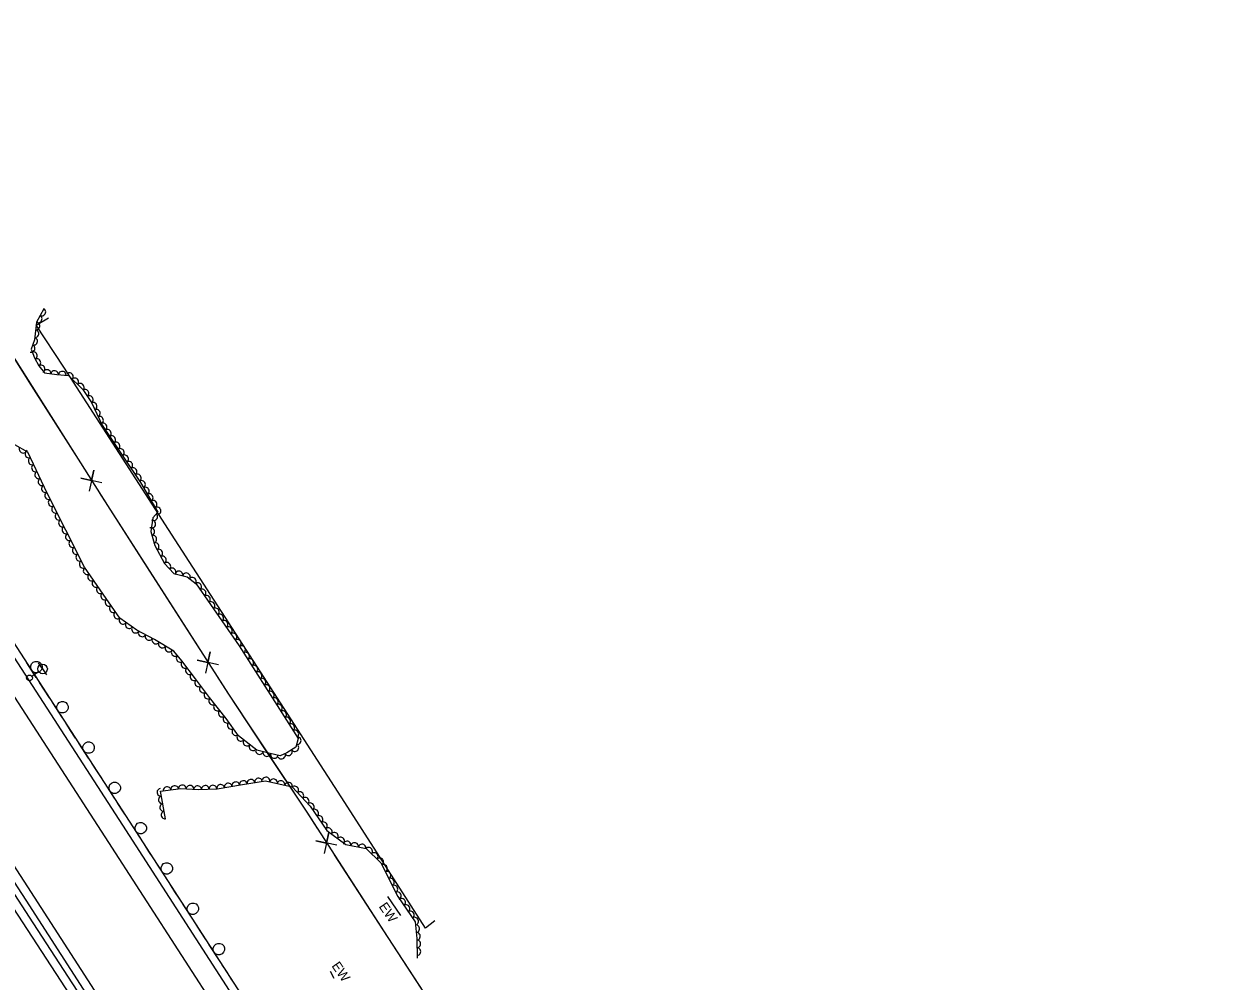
# Model space of a CAD drawing. Extents: x 1746719 to 1766531, y 631721 to 662391.
# Drawn here: x 1760642 to 1761266, y 640505 to 641004 of the extents above; entities that cross this region are included whole.
import ezdxf

# ---------------------------------------------------------------- set-up
doc = ezdxf.new("R2010")
doc.units = 0
for name, color, linetype in [('SURVEY - AERIAL SURVEY - Photo Control - Points - Elevations', 7, 'Continuous'), ('SURVEY - AERIAL SURVEY - Photo Control - Points - Numbers', 7, 'Continuous'), ('SURVEY - AERIAL SURVEY - Photo Control with Text', 7, 'Continuous'), ('SURVEY - CENTERLINE - Existing Roads - Development', 7, 'Continuous'), ('SURVEY - CENTERLINE - Existing Roads Curve Text', 7, 'Continuous'), ('SURVEY - CENTERLINE - Existing Roads Text', 7, 'Continuous'), ('SURVEY - CENTERLINE - Preliminary - Development', 7, 'Continuous')]:
    doc.layers.add(name, color=color, linetype=linetype)

msp = doc.modelspace()

# ---------------------------------------------------------------- linework, layer by layer
at = {"layer": 'SURVEY - AERIAL SURVEY - Photo Control - Points - Elevations'}
for points in [[(1761196.4, 639810.64), (1761146.73, 639886.96), (1761080.18, 639989.67), (1761013.55, 640093.35), (1760935.82, 640212.96), (1760859, 640331.61), (1760773.89, 640462.5), (1760694.04, 640586.22), (1760626.17, 640690.93), (1760539.47, 640824.63), (1760468.8, 640933.89), (1760453.88, 640957.11)], [(1761187.18, 639804.64), (1761137.51, 639880.97), (1761070.94, 639983.7), (1761004.31, 640087.38), (1760926.59, 640206.97), (1760849.77, 640325.63), (1760764.66, 640456.52), (1760684.8, 640580.25), (1760616.94, 640684.94), (1760530.24, 640818.65), (1760459.56, 640927.93), (1760444.62, 640951.16)], [(1761146.95, 639778.46), (1761097.25, 639854.83), (1761030.61, 639957.68), (1760963.99, 640061.33), (1760886.32, 640180.85), (1760809.51, 640299.5), (1760724.37, 640430.42), (1760644.5, 640554.18), (1760576.67, 640658.83), (1760489.95, 640792.56), (1760419.21, 640901.92), (1760404.24, 640925.21)], [(1760393.74, 640918.4), (1760441.13, 640845.23), (1760507.05, 640743.21), (1760565.58, 640652.81), (1760626.82, 640558.41), (1760688.54, 640463.7), (1760741.79, 640381.9), (1760794.12, 640301.16), (1760851.62, 640212.52), (1760925.86, 640097.46), (1760981.18, 640012.09), (1761038.81, 639922.4), (1761095.32, 639835.55), (1761136.33, 639771.93)], [(1760856.45, 640536.45), (1760851.59, 640532.66), (1760811.17, 640595.61), (1760765.67, 640666.2), (1760721.15, 640734.98), (1760663.16, 640824.86), (1760648.84, 640846.78), (1760655.25, 640850.56)]]:
    msp.add_lwpolyline(points, dxfattribs=at)
at = {"layer": 'SURVEY - AERIAL SURVEY - Photo Control - Points - Numbers'}
for points in [[(1761140.67, 639773.85), (1761073.58, 639878.26), (1760990.71, 640006.56), (1760880.55, 640175.62), (1760768.9, 640348.2), (1760647.19, 640535.4), (1760552.29, 640681.96), (1760459.27, 640825.92), (1760396.33, 640923.21)], [(1760398.55, 640924.9), (1760464.19, 640823.64), (1760557.54, 640679.57), (1760643.46, 640547.14), (1760726.42, 640418.31), (1760797.81, 640309.01), (1760889.3, 640167.21), (1760984.42, 640021.34), (1761065.75, 639894.94), (1761143.02, 639775.73)], [(1760925.05, 640236.95), (1760862.35, 640333.79), (1760777.25, 640464.67), (1760697.4, 640588.39), (1760623.82, 640701.9)], [(1760648.9, 640663.22), (1760643.89, 640670.94)], [(1760653.2, 640656.59), (1760650.64, 640660.53)], [(1760655.75, 640652.65), (1760653.2, 640656.59)], [(1760662.5, 640642.24), (1760657.49, 640649.96)], [(1760666.79, 640635.61), (1760664.24, 640639.55)], [(1760669.35, 640631.67), (1760666.79, 640635.61)], [(1760676.09, 640621.26), (1760671.09, 640628.98)], [(1760680.39, 640614.63), (1760677.83, 640618.58)], [(1760682.95, 640610.69), (1760680.39, 640614.63)], [(1760689.69, 640600.28), (1760684.69, 640608)], [(1760693.99, 640593.65), (1760691.43, 640597.6)], [(1760696.54, 640589.71), (1760693.99, 640593.65)], [(1760703.27, 640579.29), (1760698.28, 640587.02)], [(1760707.55, 640572.66), (1760705.01, 640576.6)], [(1760710.1, 640568.71), (1760707.55, 640572.66)], [(1760716.83, 640558.29), (1760711.84, 640566.02)], [(1760721.11, 640551.65), (1760718.56, 640555.6)], [(1760723.66, 640547.7), (1760721.11, 640551.65)], [(1760730.39, 640537.28), (1760725.4, 640545.01)], [(1760734.67, 640530.65), (1760732.12, 640534.59)], [(1760737.22, 640526.7), (1760734.67, 640530.65)], [(1760743.94, 640516.28), (1760738.95, 640524.01)], [(1760748.23, 640509.64), (1760745.68, 640513.59)], [(1760750.77, 640505.69), (1760748.23, 640509.64)]]:
    msp.add_lwpolyline(points, dxfattribs=at)
for centre, start, end in [((1760648.94, 640668.67), 326.21851, 326.20452), ((1760662.54, 640647.69), 326.21851, 326.20452), ((1760676.13, 640626.72), 326.21851, 326.20452), ((1760689.73, 640605.74), 326.21851, 326.20452), ((1760703.32, 640584.75), 326.10698, 326.093), ((1760716.88, 640563.74), 326.10698, 326.093), ((1760730.43, 640542.74), 326.10698, 326.093), ((1760743.99, 640521.73), 326.10698, 326.093)]:
    msp.add_arc(centre, 3, start, end, dxfattribs=at)
at = {"layer": 'SURVEY - AERIAL SURVEY - Photo Control with Text'}
for points in [[(1760652.8, 640855.32), (1760649.07, 640848.29), (1760647.88, 640839.12), (1760646.16, 640834.17), (1760647.95, 640829.76), (1760650.29, 640825.51), (1760653.15, 640821.88), (1760659.59, 640820.97), (1760665.62, 640820.59), (1760673.09, 640813.22), (1760677.66, 640806.53), (1760683.18, 640794.6), (1760694.39, 640778.05), (1760703.24, 640764.75), (1760712.26, 640749.31), (1760709.68, 640746.36), (1760708.59, 640739.29), (1760710.64, 640731.98), (1760715.72, 640722.6), (1760720.5, 640717.38), (1760727.46, 640715.68), (1760732.09, 640711.96), (1760754.62, 640679.75), (1760785.21, 640631.37), (1760784.01, 640626.84), (1760779.46, 640623.97), (1760775.84, 640622.35), (1760770.7, 640623.55), (1760763.77, 640625.42), (1760754.17, 640632.89), (1760747.82, 640641.88), (1760739.17, 640652.85), (1760731.76, 640662.53), (1760724.77, 640671.94), (1760720.57, 640676.86), (1760710.44, 640683.05), (1760701.2, 640687.84), (1760692.42, 640694.05), (1760683.71, 640706.63), (1760674, 640720.66), (1760654.63, 640759.17), (1760644.46, 640780.64), (1760637.69, 640784.42)], [(1760716.22, 640589.64), (1760713.6, 640603.96), (1760724.16, 640605.36), (1760733.14, 640604.88), (1760743.08, 640605.29), (1760756.27, 640607.51), (1760768.2, 640609.47), (1760782.11, 640606.19), (1760791.46, 640596.23), (1760800.24, 640583.55), (1760810.05, 640576.21), (1760820.72, 640574.07), (1760828.34, 640566.74), (1760837.16, 640549.22), (1760846.29, 640536.02), (1760847.09, 640527.3), (1760847.34, 640517.01)]]:
    msp.add_lwpolyline(points, dxfattribs=at)
for centre, major_axis in [((1760651.87, 640853.55), (-0.94, -1.77)), ((1760648.81, 640846.26), (-0.26, -1.98)), ((1760649.99, 640850.02), (-0.94, -1.77)), ((1760648.29, 640842.3), (-0.26, -1.98)), ((1760646.3, 640834.59), (-0.66, -1.89)), ((1760647.62, 640838.37), (-0.66, -1.89)), ((1760647.5, 640830.88), (0.75, -1.85)), ((1760649.3, 640827.31), (0.96, -1.75)), ((1760651.49, 640823.98), (1.24, -1.57)), ((1760654.46, 640821.7), (1.98, -0.28)), ((1760658.42, 640821.14), (1.98, -0.28)), ((1760662.4, 640820.8), (2, -0.13)), ((1760666.17, 640820.04), (1.42, -1.4)), ((1760669.02, 640817.24), (1.42, -1.4)), ((1760671.87, 640814.43), (1.42, -1.4)), ((1760674.38, 640811.34), (1.13, -1.65)), ((1760676.63, 640808.03), (1.13, -1.65)), ((1760678.57, 640804.55), (0.84, -1.82)), ((1760680.25, 640800.92), (0.84, -1.82)), ((1760681.93, 640797.29), (0.84, -1.82)), ((1760683.76, 640793.74), (1.12, -1.66)), ((1760686, 640790.43), (1.12, -1.66)), ((1760688.24, 640787.12), (1.12, -1.66)), ((1760690.49, 640783.81), (1.12, -1.66)), ((1760641.97, 640782.03), (-1.75, 0.97)), ((1760644.95, 640779.6), (-0.86, 1.81)), ((1760692.73, 640780.5), (1.12, -1.66)), ((1760694.97, 640777.18), (1.11, -1.66)), ((1760646.66, 640775.98), (-0.86, 1.81)), ((1760648.38, 640772.37), (-0.86, 1.81)), ((1760697.18, 640773.85), (1.11, -1.66)), ((1760699.4, 640770.52), (1.11, -1.66)), ((1760650.09, 640768.76), (-0.86, 1.81)), ((1760651.8, 640765.14), (-0.86, 1.81)), ((1760701.62, 640767.19), (1.11, -1.66)), ((1760703.78, 640763.83), (1.01, -1.73)), ((1760653.51, 640761.53), (-0.86, 1.81)), ((1760655.25, 640757.92), (-0.9, 1.79)), ((1760705.8, 640760.37), (1.01, -1.73)), ((1760657.05, 640754.35), (-0.9, 1.79)), ((1760707.82, 640756.92), (1.01, -1.73)), ((1760709.83, 640753.47), (1.01, -1.73)), ((1760658.85, 640750.78), (-0.9, 1.79)), ((1760660.65, 640747.21), (-0.9, 1.79)), ((1760710.16, 640746.91), (-1.32, -1.5)), ((1760711.85, 640750.01), (1.01, -1.73)), ((1760662.45, 640743.63), (-0.9, 1.79)), ((1760664.24, 640740.06), (-0.9, 1.79)), ((1760708.62, 640739.18), (0.54, -1.93)), ((1760709.18, 640743.13), (-0.31, -1.98)), ((1760666.04, 640736.49), (-0.9, 1.79)), ((1760667.84, 640732.91), (-0.9, 1.79)), ((1760709.7, 640735.33), (0.54, -1.93)), ((1760669.64, 640729.34), (-0.9, 1.79)), ((1760710.88, 640731.52), (0.95, -1.76)), ((1760712.79, 640728.01), (0.95, -1.76)), ((1760671.44, 640725.77), (-0.9, 1.79)), ((1760673.23, 640722.19), (-0.9, 1.79)), ((1760714.7, 640724.49), (0.95, -1.76)), ((1760716.97, 640721.23), (1.35, -1.48)), ((1760675.3, 640718.78), (-1.14, 1.64)), ((1760677.58, 640715.49), (-1.14, 1.64)), ((1760719.67, 640718.28), (1.35, -1.48)), ((1760723.19, 640716.72), (1.94, -0.47)), ((1760727.08, 640715.77), (1.94, -0.47)), ((1760679.86, 640712.2), (-1.14, 1.64)), ((1760682.13, 640708.91), (-1.14, 1.64)), ((1760730.27, 640713.42), (1.56, -1.25)), ((1760733.05, 640710.59), (1.15, -1.64)), ((1760735.34, 640707.32), (1.15, -1.64)), ((1760684.41, 640705.62), (-1.14, 1.64)), ((1760686.68, 640702.33), (-1.14, 1.64)), ((1760737.63, 640704.04), (1.15, -1.64)), ((1760688.96, 640699.05), (-1.14, 1.64)), ((1760691.24, 640695.76), (-1.14, 1.64)), ((1760739.92, 640700.76), (1.15, -1.64)), ((1760742.22, 640697.48), (1.15, -1.64)), ((1760693.99, 640692.94), (-1.63, 1.15)), ((1760697.25, 640690.63), (-1.63, 1.15)), ((1760744.51, 640694.21), (1.15, -1.64)), ((1760746.8, 640690.93), (1.15, -1.64)), ((1760700.52, 640688.32), (-1.63, 1.15)), ((1760704.01, 640686.38), (-1.78, 0.92)), ((1760707.56, 640684.54), (-1.78, 0.92)), ((1760749.09, 640687.65), (1.15, -1.64)), ((1760751.39, 640684.37), (1.15, -1.64)), ((1760711.09, 640682.65), (-1.71, 1.04)), ((1760714.5, 640680.57), (-1.71, 1.04)), ((1760717.92, 640678.48), (-1.71, 1.04)), ((1760753.68, 640681.09), (1.15, -1.64)), ((1760755.88, 640677.76), (1.07, -1.69)), ((1760721.15, 640676.19), (-1.3, 1.52)), ((1760723.74, 640673.14), (-1.3, 1.52)), ((1760758.02, 640674.37), (1.07, -1.69)), ((1760760.16, 640670.99), (1.07, -1.69)), ((1760726.21, 640669.99), (-1.19, 1.61)), ((1760728.6, 640666.78), (-1.19, 1.61)), ((1760762.29, 640667.61), (1.07, -1.69)), ((1760764.43, 640664.23), (1.07, -1.69)), ((1760730.98, 640663.57), (-1.19, 1.61)), ((1760733.4, 640660.39), (-1.22, 1.59)), ((1760766.57, 640660.85), (1.07, -1.69)), ((1760768.71, 640657.47), (1.07, -1.69)), ((1760735.83, 640657.21), (-1.22, 1.59)), ((1760738.26, 640654.03), (-1.22, 1.59)), ((1760770.84, 640654.09), (1.07, -1.69)), ((1760740.72, 640650.88), (-1.24, 1.57)), ((1760743.2, 640647.74), (-1.24, 1.57)), ((1760772.98, 640650.71), (1.07, -1.69)), ((1760775.12, 640647.33), (1.07, -1.69)), ((1760745.67, 640644.6), (-1.24, 1.57)), ((1760748.13, 640641.44), (-1.15, 1.63)), ((1760777.26, 640643.95), (1.07, -1.69)), ((1760779.39, 640640.57), (1.07, -1.69)), ((1760750.44, 640638.17), (-1.15, 1.63)), ((1760752.75, 640634.91), (-1.15, 1.63)), ((1760781.53, 640637.18), (1.07, -1.69)), ((1760783.67, 640633.8), (1.07, -1.69)), ((1760755.38, 640631.95), (-1.58, 1.23)), ((1760758.53, 640629.49), (-1.58, 1.23)), ((1760784.92, 640630.29), (-0.51, -1.93)), ((1760761.69, 640627.04), (-1.58, 1.23)), ((1760765.09, 640625.07), (-1.93, 0.52)), ((1760768.95, 640624.02), (-1.93, 0.52)), ((1760772.83, 640623.05), (-1.95, 0.46)), ((1760776.67, 640622.72), (-1.83, -0.81)), ((1760780.26, 640624.47), (-1.69, -1.07)), ((1760783.64, 640626.61), (-1.69, -1.07)), ((1760756.73, 640607.59), (1.97, 0.33)), ((1760760.67, 640608.24), (1.97, 0.33)), ((1760764.62, 640608.89), (1.97, 0.33)), ((1760768.56, 640609.39), (1.95, -0.46)), ((1760772.46, 640608.47), (1.95, -0.46)), ((1760776.35, 640607.55), (1.95, -0.46)), ((1760713.7, 640603.41), (-0.36, 1.97)), ((1760717, 640604.41), (1.98, 0.26)), ((1760720.97, 640604.94), (1.98, 0.26)), ((1760724.94, 640605.32), (2, -0.11)), ((1760728.93, 640605.11), (2, -0.11)), ((1760732.93, 640604.89), (2, -0.11)), ((1760736.92, 640605.04), (2, 0.08)), ((1760740.92, 640605.2), (2, 0.08)), ((1760744.89, 640605.6), (1.97, 0.33)), ((1760748.84, 640606.26), (1.97, 0.33)), ((1760752.78, 640606.92), (1.97, 0.33)), ((1760780.24, 640606.63), (1.95, -0.46)), ((1760783.53, 640604.67), (1.37, -1.46)), ((1760786.27, 640601.76), (1.37, -1.46)), ((1760714.42, 640599.47), (-0.36, 1.97)), ((1760715.14, 640595.54), (-0.36, 1.97)), ((1760789.01, 640598.84), (1.37, -1.46)), ((1760791.7, 640595.89), (1.14, -1.64)), ((1760715.86, 640591.61), (-0.36, 1.97)), ((1760793.98, 640592.6), (1.14, -1.64)), ((1760796.25, 640589.31), (1.14, -1.64)), ((1760798.53, 640586.02), (1.14, -1.64)), ((1760801.04, 640582.95), (1.6, -1.2)), ((1760804.24, 640580.56), (1.6, -1.2)), ((1760807.44, 640578.16), (1.6, -1.2)), ((1760810.78, 640576.06), (1.96, -0.39)), ((1760814.7, 640575.28), (1.96, -0.39)), ((1760818.62, 640574.49), (1.96, -0.39)), ((1760822.06, 640572.78), (1.44, -1.39)), ((1760824.94, 640570.01), (1.44, -1.39)), ((1760827.83, 640567.23), (1.44, -1.39)), ((1760829.82, 640563.8), (0.9, -1.79)), ((1760831.62, 640560.23), (0.9, -1.79)), ((1760833.41, 640556.66), (0.9, -1.79)), ((1760835.21, 640553.08), (0.9, -1.79)), ((1760837.01, 640549.51), (0.9, -1.79)), ((1760839.25, 640546.2), (1.14, -1.64)), ((1760841.52, 640542.91), (1.14, -1.64)), ((1760843.8, 640539.62), (1.14, -1.64)), ((1760846.07, 640536.33), (1.14, -1.64)), ((1760846.62, 640532.41), (0.18, -1.99)), ((1760846.99, 640528.43), (0.18, -1.99)), ((1760847.16, 640524.43), (0.05, -2)), ((1760847.26, 640520.43), (0.05, -2))]:
    msp.add_ellipse(centre, major_axis=major_axis, ratio=0.940188, start_param=0, end_param=3.141593, dxfattribs=at)
at = {"layer": 'SURVEY - CENTERLINE - Existing Roads - Development'}
for p, q in [((1760646.6, 640663.84), (1760650.1, 640666.26)), ((1760652.16, 640667.68), (1760650.02, 640670.77)), ((1760652.16, 640667.68), (1760654.29, 640664.6))]:
    msp.add_line(p, q, dxfattribs=at)
for centre, radius in [((1760652.16, 640667.68), 2.5), ((1760645.37, 640662.99), 1.5)]:
    msp.add_circle(centre, radius, dxfattribs=at)
at = {"layer": 'SURVEY - CENTERLINE - Existing Roads Curve Text'}
for points in [[(1760523.13, 641003.67), (1760556.48, 640952.68), (1760587.17, 640905.73), (1760622.62, 640852.72), (1760686.01, 640752.79), (1760748.96, 640654.51), (1760789.73, 640592.99), (1760831.97, 640527.72), (1760882.49, 640450.37), (1760943.59, 640353.92), (1761014.04, 640244.82), (1761096.19, 640117.07), (1761186.71, 639977.91), (1761265.97, 639858.91)], [(1760621.4, 640854.54), (1760622.62, 640852.72), (1760646.3, 640815.39)], [(1760646.3, 640815.39), (1760673.08, 640773.16)], [(1760683.12, 640764.61), (1760672.14, 640767), (1760677.66, 640765.76), (1760678.89, 640771.28), (1760676.37, 640760.33)], [(1760681.71, 640759.57), (1760686.01, 640752.79), (1760706.7, 640720.48)], [(1760706.7, 640720.48), (1760733.67, 640678.37)], [(1760743.75, 640669.87), (1760732.76, 640672.2), (1760738.28, 640670.99), (1760739.49, 640676.52), (1760737.02, 640665.55)], [(1760742.36, 640664.82), (1760748.96, 640654.51), (1760767.83, 640626.04)], [(1760767.83, 640626.04), (1760789.73, 640592.99), (1760795.36, 640584.3)], [(1760805.48, 640575.84), (1760794.47, 640578.12), (1760800, 640576.94), (1760801.18, 640582.47), (1760798.76, 640571.49)], [(1760804.1, 640570.78), (1760829.32, 640531.83)], [(1760829.32, 640531.83), (1760831.97, 640527.72), (1760856.64, 640489.95)]]:
    msp.add_lwpolyline(points, dxfattribs=at)
at = {"layer": 'SURVEY - CENTERLINE - Existing Roads Text'}
for points in [[(1760831.76, 640549.07), (1760838.57, 640539.29)], [(1760801.98, 640510.28), (1760803.95, 640506.67)]]:
    msp.add_lwpolyline(points, dxfattribs=at)

# ---------------------------------------------------------------- texts
at = {"layer": 'SURVEY - CENTERLINE - Preliminary - Development'}
for rotation, p in [(304.6811, (1760827.09, 640543.91)), (304.68145, (1760802.48, 640513.01))]:
    msp.add_text('EW', height=5, rotation=rotation, dxfattribs=at).set_placement(p)

doc.saveas('drawing.dxf')
